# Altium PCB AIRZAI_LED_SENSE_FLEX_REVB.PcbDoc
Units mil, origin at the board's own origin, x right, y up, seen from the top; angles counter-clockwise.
Board outline 2713.44 x 4393.69 mil, 2 copper layers (Top Layer, Bottom Layer); 51 components, 36 nets, 158 pads, 68 vias.
Unrouted connection lines stored in the file: 83.
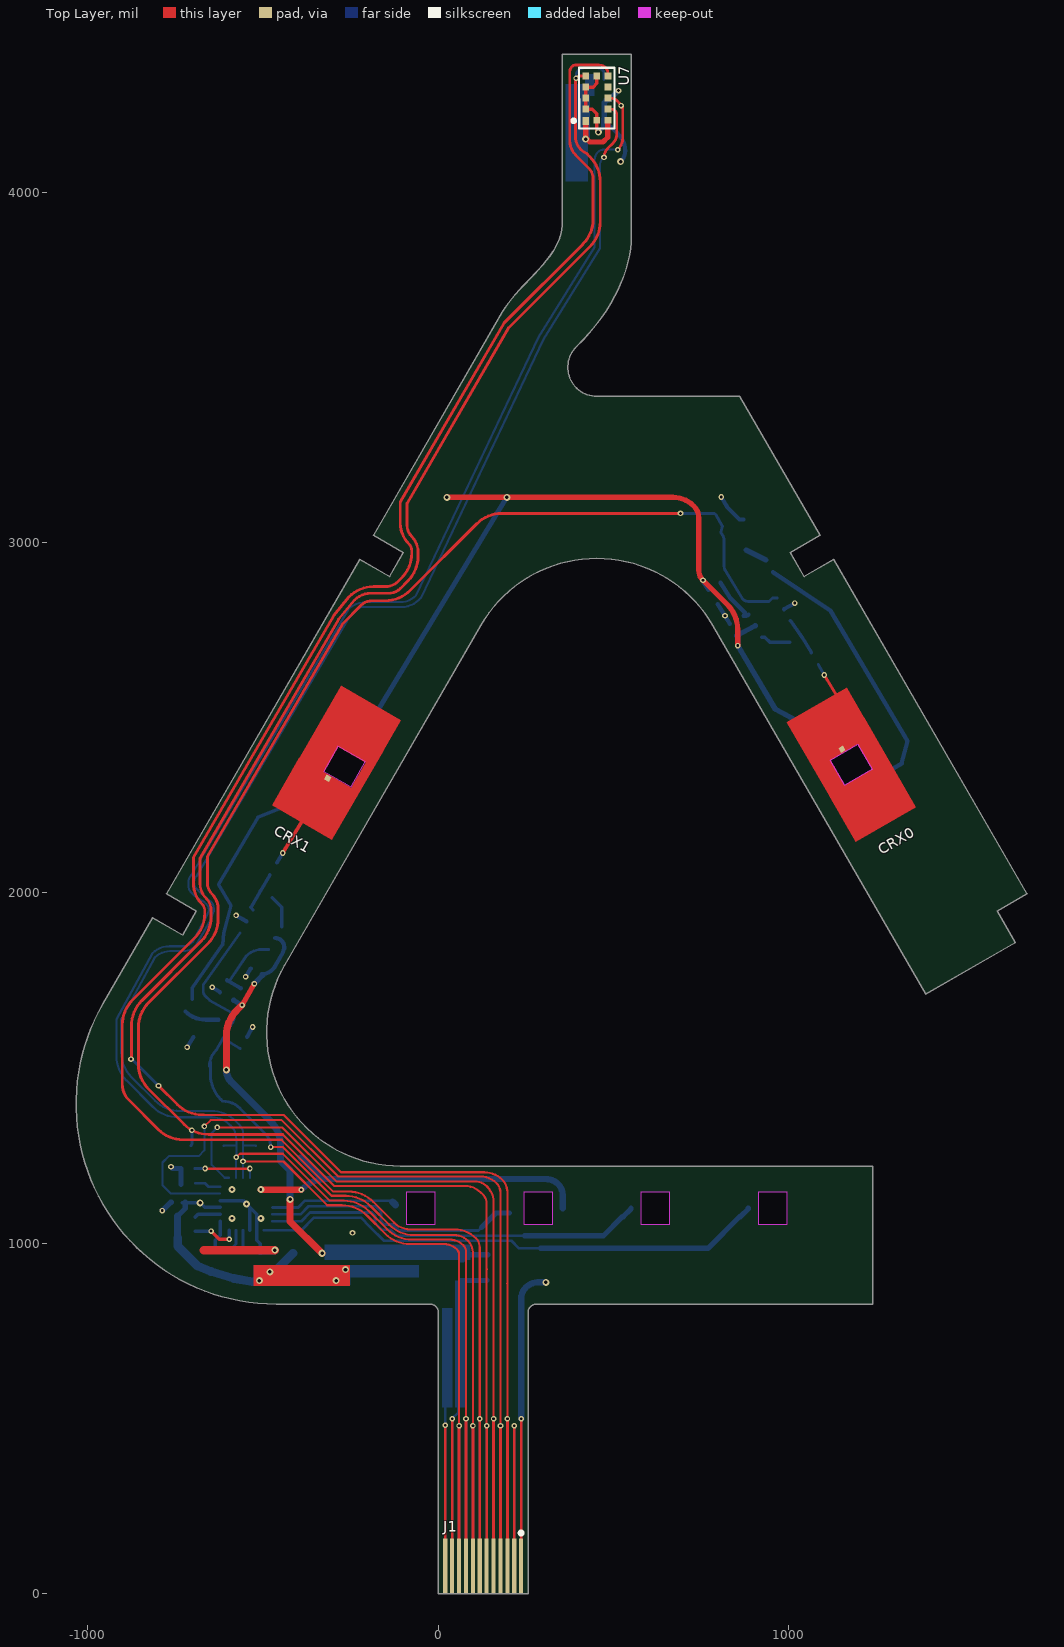
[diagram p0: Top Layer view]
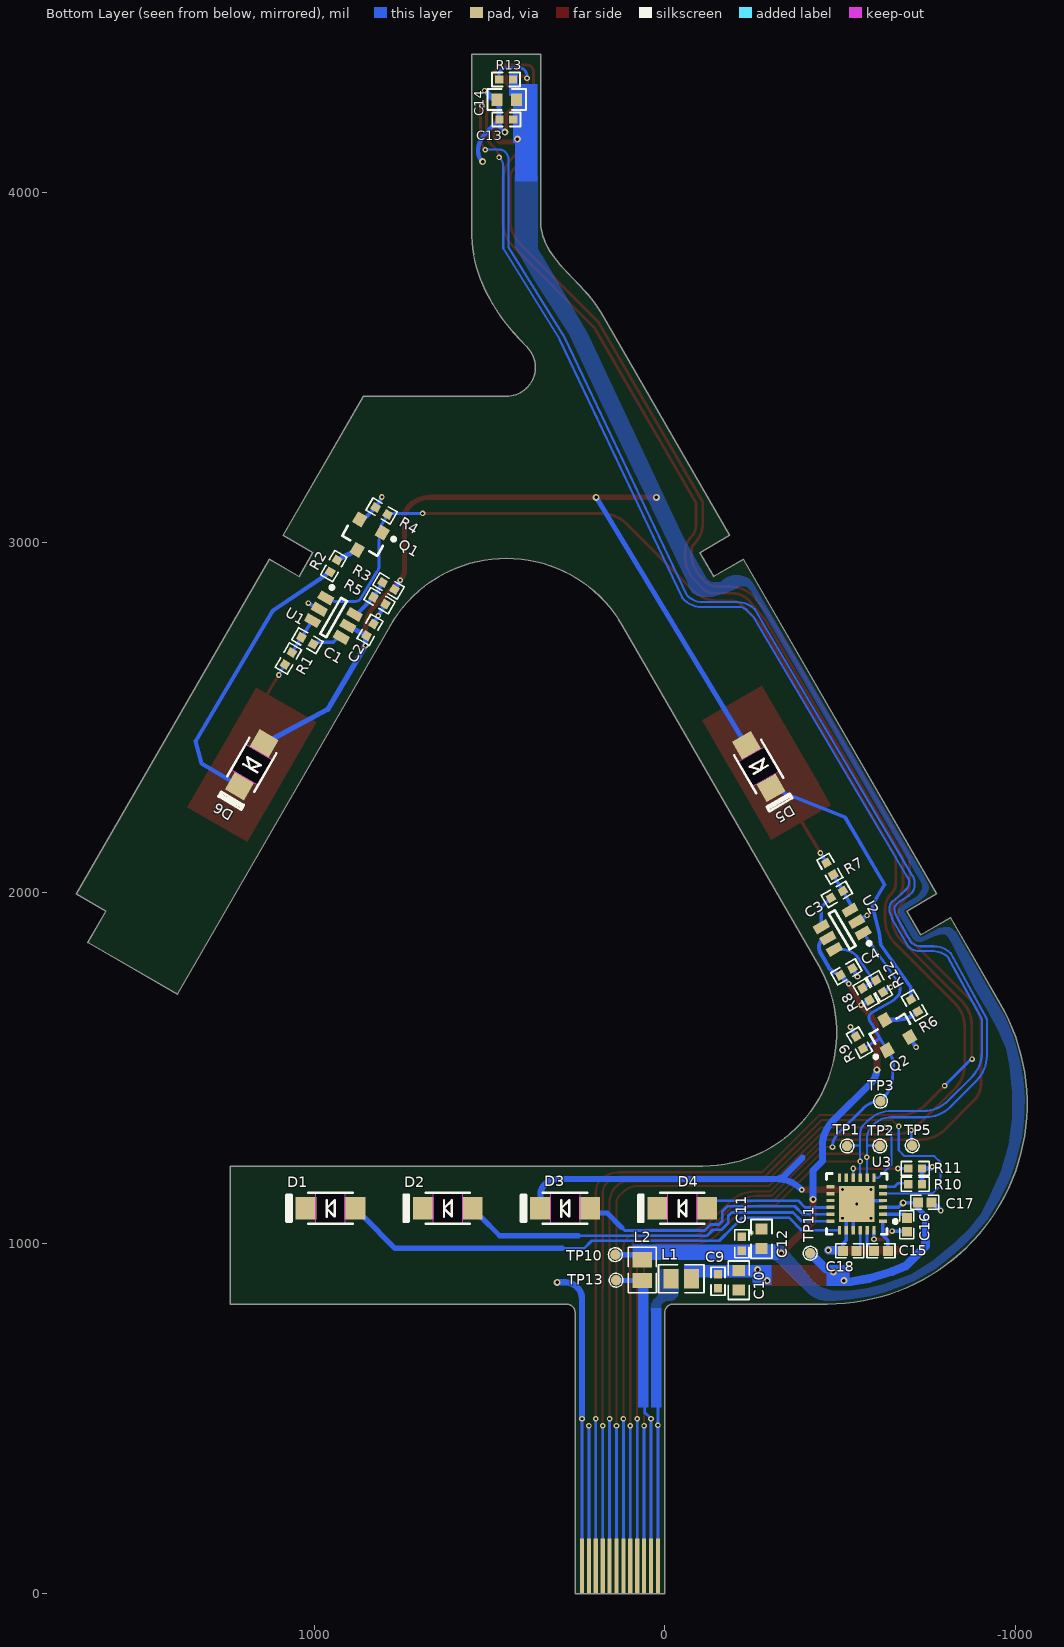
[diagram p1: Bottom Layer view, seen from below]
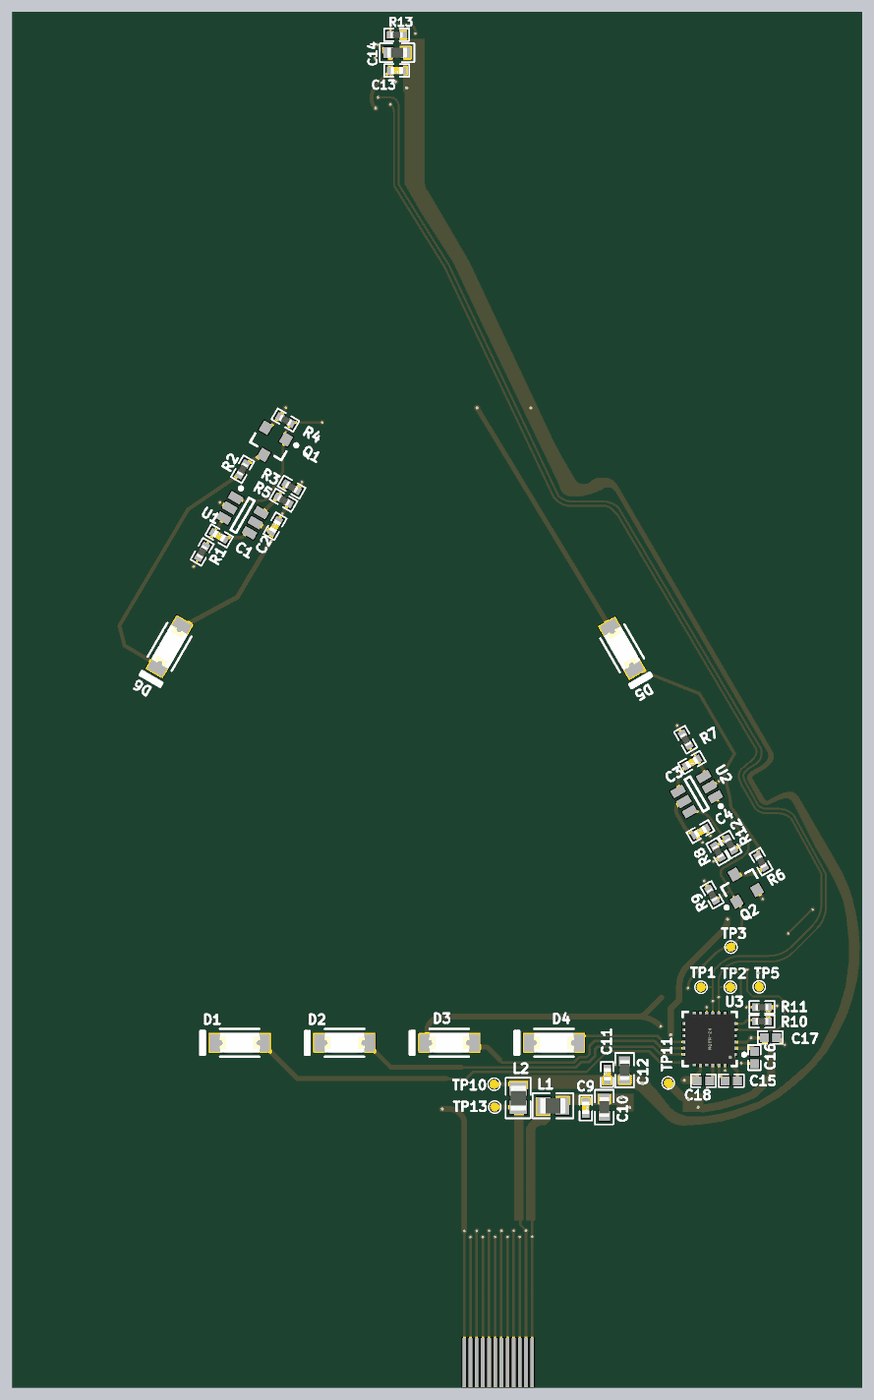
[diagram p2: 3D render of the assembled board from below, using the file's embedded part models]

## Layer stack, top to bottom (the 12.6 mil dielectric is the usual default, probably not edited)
Top Solder: solder mask 0.4, Solder Resist, Dk 3.5
Top Layer: signal copper 1.4
Dielectric 1: dielectric 12.6, FR-4, Dk 4.8
Bottom Layer: signal copper 1.4
Bottom Solder: solder mask 0.4, Solder Resist, Dk 3.5

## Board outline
-463,826.78 cw(c-462.98,1397.65) -957.36,1683.09 -815.14,1929.41 -729.91,1880.19 -690.53,1948.38 -775.77,1997.6 -224.58,2952.23 -139.35,2903.01 -99.97,2971.2 -185.21,3020.41 182.62,3657.47 cw(c465.09,3488.64) 220.1,3708.36 cw(c839.65,3165.01) 242.17,3732.54 264.96,3756.39 ccw(c-627.68,4615.35) 287.35,3780.27 ccw(c-93.59,4128.16) 308.19,3804.57 ccw(c73.79,3993.55) 326.37,3829.65 ccw(c158.18,3938.86) 340.75,3855.9 ccw(c204.05,3917.92) 350.2,3883.68 ccw(c222.06,3913.41) 353.61,3913.38 353.61,3952.75 353.61,4393.69 550.46,4393.69 550.46,3952.74 550.46,3874 cw(c239.31,3875.17) 542.24,3804.11 cw(c183.5,3887.15) 532.52,3769.79 cw(c138.88,3902.12) 519.55,3736.13 cw(c91.77,3922.61) 503.7,3703.33 cw(c24.31,3959.43) 464.84,3641.1 cw(c-49.74,4012.89) 394.16,3559.04 ccw(c452.02,3499.99) 452.02,3417.31 860.08,3417.3 1089.23,3020.38 1003.99,2971.17 1043.36,2902.98 1128.6,2952.19 1679.74,1997.53 1594.5,1948.32 1646.29,1858.61 1390.38,1711.31 782.73,2763.85 ccw(c452,2572.92) 121.28,2763.87 -439.1,1793.32 ccw(c-108.38,1602.36) -108.39,1220.47 1239.37,1220.44 1239.37,826.77 279.66,826.77 ccw(c279.78,802.89) 255.91,802.77 255.91,0 0,0 0,802.41 ccw(c-23.88,802.89) -23.39,826.77
cut-out: 912.59,1055.11 995.26,1055.11 995.26,1145.66 912.59,1145.66
cut-out: 577.94,1055.12 660.62,1055.12 660.62,1145.67 577.94,1145.67
cut-out: 243.3,1055.12 325.97,1055.12 325.97,1145.67 243.3,1145.67
cut-out: -91.36,1055.12 -8.68,1055.12 -8.68,1145.67 -91.36,1145.67
cut-out: 1159.59,2307.55 1118.49,2378.93 1196.97,2424.11 1238.06,2352.73
cut-out: -327.65,2347.93 -249.18,2302.74 -208.08,2374.12 -286.55,2419.3

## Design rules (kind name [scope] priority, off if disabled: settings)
Clearance Clearance_Board_Cutout_Electrodes [(InComponent('CRX0') OR InComponent('CRX1')) vs OnLayer('Multi-Layer')] p1: gap=0 ignorepadtopadclearanceinfootprint=FALSE
Clearance Clearance_Board_Cutout_Diodes [(InComponent('D1') OR InComponent('D2') OR InComponent('D3') OR InComponent('D4') OR InComponent('D5') OR InComponent('D6')) vs OnLayer('Multi-Layer')] p2: gap=0 ignorepadtopadclearanceinfootprint=FALSE
Clearance Clearance_Keepout [(OnLayer('Keep-Out Layer')) vs (InComponent('D1') OR InComponent('D2') OR InComponent('D3') OR InComponent('D4') OR InComponent('D5') OR InComponent('D6') OR InComponent('CRX0') OR InComponent('CRX1') OR InComponent('J1'))] p3: gap=0 ignorepadtopadclearanceinfootprint=FALSE
Clearance Clearance_GND_POLY_ELECTRODE [(InComponent('CRX0') OR InComponent('CRX1') OR InComponent('CRX2') OR InNet('NetCRX0_1') OR InNet('NetCRX1_1') OR InNet('NetCRX2_1') OR InNet('NetR4_2') OR InNet('NetR2_1') OR InNet('NetR1_1')) vs (InNet('GND') AND InPolygon)] p4: gap=30 ignorepadtopadclearanceinfootprint=FALSE
Clearance Clearance_POLYGON_KEEPOUT [(OnLayer('Keep-Out Layer')) vs (InNet('GND') AND InPolygon)] p5: gap=10 ignorepadtopadclearanceinfootprint=FALSE
Clearance Clearance_GND_POLY_REST [All vs (InNet('GND') AND InPolygon)] p6: gap=10 ignorepadtopadclearanceinfootprint=FALSE
Clearance [All] p7: gap=6 ignorepadtopadclearanceinfootprint=FALSE
MinimumSolderMaskSliver [All] p1: minsoldermaskwidth=1
PolygonConnect [All] p1: connectstyle=Direct reliefconductorwidth=10 reliefentries=4 polygonreliefangle="90 Angle" airgapwidth=10
RoomDefinition AIRZAI_LED_SENSE_FLEX_REVB [InComponentClass('AIRZAI_LED_SENSE_FLEX_REVB')] p1: confinementstyle=ConfineIn formatcopy=TRUE lockcomponents=FALSE outline -3892.14,-2713.97 10767.86,-2713.97 10767.86,6886.03 -3892.14,6886.03
RoutingVias [All] p1: holewidth=28 width=50 viastyle="Through Hole" minholewidth=8 minwidth=16 maxholewidth=28 maxwidth=50
SilkToSilkClearance [All] p1: silktosilkclearance=1
SilkToSolderMaskClearance [IsPad] p1: minsilkscreentomaskgap=2 clearancetoexposedcopper=TRUE
SolderMaskExpansion [All] p1: expansion=4
UnRoutedNet [All] p1: checkbadconnections=TRUE
Width [All] p1: maxlimit=100 minlimit=6 preferedwidth=10
26 further rules are at their usual default settings.

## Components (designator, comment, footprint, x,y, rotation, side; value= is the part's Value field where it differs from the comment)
C1 "22nF" 0402CAP 1020,2720 r210 bottom
C2 "0.1µF" 0402CAP 841,2751 r120 bottom
C3 "22nF" 0402CAP -491,1996 r330 bottom
C4 "0.1µF" 0402CAP -518.16,1775.08 r150 bottom
C9 "0.1µF" 0402CAP -152,892.17 r270 bottom
C10 "10µF" 0603 -211,895 r270 bottom
C11 "0.1µF" 0402CAP -220,999.22 r90 bottom
C12 "10µF" 0603 -276,1013 r90 bottom
C13 "0.1µF" 0402CAP 452.01,4207.25 r0 bottom
C14 "4.7µF" 0603 451,4264 r180 bottom
C15 "CAP 1uF 16V 0402(1005)" CAPC0402(1005)60_M -616.69,979 r0 bottom value=1uF
C16 "CAP 1uF 16V 0402(1005)" CAPC0402(1005)60_M -690.55,1053.06 r270 bottom value=1uF
C17 "CAP 1uF 16V 0402(1005)" CAPC0402(1005)60_M -741.73,1117.23 r0 bottom value=1uF
C18 "CAP 1uF 16V 0402(1005)" CAPC0402(1005)60_M -527.69,979 r0 bottom value=1uF
CRX0 "CONTACT POINT 1" "CONTACT_POINT_1CM _SQ - duplicate" 1178.28,2365.83 r300 top
CRX1 "CONTACT POINT 1" "CONTACT_POINT_1CM _SQ" -290.35,2372.21 r60 top
D1 "WHITE" LED1206_LTW-C230DS 953.93,1100.39 r0 bottom locked
D2 "WHITE" LED1206_LTW-C230DS 619.28,1100.4 r0 bottom locked
D3 "WHITE" LED1206_LTW-C230DS 284.63,1100.41 r0 bottom locked
D4 "WHITE" LED1206_LTW-C230DS -50.03,1100.42 r0 bottom
D5 "WHITE" LED1206_LTW-C230DS -267.86,2361.02 r240 bottom
D6 "WHITE" LED1206_LTW-C230DS 1178.28,2365.83 r300 bottom
J1 "FFC Pads" FFC_PADS 127.95,78.74 r0 top locked
L1 "CB2012T100KR" 0805 -47,899 r180 bottom value=10uH
L2 "CB2012T100KR" 0805 64,924 r90 bottom value=10uH
Q1 "NTR4003NT1G" SOT-23-3-NTR4003NT1G 858,3013 r300 bottom
Q2 "NTR4003NT1G" SOT-23-3-NTR4003NT1G -647,1604 r60 bottom
R1 "10k 0402(1005)" 0402 1074,2669 r300 bottom value=10k
R2 "100R 0402(1005)" 0402 944.64,2933 r300 bottom value=100
R3 "Jumper 0402(1005)" 0402 788.11,2876 r210 bottom value=0R
R4 "DNP 0402(1005)" 0402 808,3090 r30 bottom value=DNP
R5 "DNP 0402(1005)" 0402 814,2834 r210 bottom value=DNP
R6 "100R 0402(1005)" 0402 -712,1679.08 r60 bottom value=100
R7 "10k 0402(1005)" 0402 -471,2069 r60 bottom value=10k
R8 "Jumper 0402(1005)" 0402 -574.02,1711 r240 bottom value=0R
R9 "DNP 0402(1005)" 0402 -555.51,1573 r60 bottom value=DNP
R10 "Jumper 0402(1005)" 0402 -714.57,1168.99 r0 bottom value=0R
R11 "Jumper 0402(1005)" 0402 -714.57,1213.99 r0 bottom value=0R
R12 "DNP 0402(1005)" 0402 -613,1734 r240 bottom value=DNP
R13 "10k 0402(1005)" 0402 453,4321 r0 bottom value=10k
TP1 "Test Point" TP_0.9MM -520.09,1278 r90 bottom
TP2 "Test Point" TP_0.9MM -613.6,1278 r90 bottom
TP3 "Test Point" TP_0.9MM -615.68,1406 r90 bottom
TP5 "Test Point" TP_0.9MM -706,1279 r90 bottom
TP10 "Test Point" TP_0.9MM 141,968 r90 bottom
TP11 "Test Point" TP_0.9MM -415,972 r90 bottom
TP13 "Test Point" TP_0.9MM 139,895 r90 bottom
U1 "AT42QT1010-TSHR" SOT-23-6-AT42QT1010-TSHR 944.94,2785.89 r210 bottom
U2 "AT42QT1010-TSHR" SOT-23-6-AT42QT1010-TSHR -506.3,1895 r330 bottom
U3 "LP55231SQE/NOPB" WQFN-24-LP55231SQE/NOPB -547.74,1112.61 r0 bottom value="IC LED DRIVER RGLTR DIM 24WQFN"
U7 "VL53L0CXV0DH/1" VL53L0X 452,4268 r270 top

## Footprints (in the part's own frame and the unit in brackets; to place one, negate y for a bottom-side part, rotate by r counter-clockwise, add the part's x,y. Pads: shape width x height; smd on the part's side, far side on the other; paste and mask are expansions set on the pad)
0402 [mm] "Chip Resistor, Body 1.1x0.5mm, IPC High Density"
  rect 0.6x0.6 smd: 1(-0.5,0) 2(0.5,0)
  silkscreen extent -1.02,-0.51 1.02,0.51, body extent -0.5,-0.25 0.5,0.25, height 0.27
0402CAP [mm] "Chip Capacitor, Body 1.1x0.5mm, IPC High Density"
  rect 0.6x0.6 smd: 1(-0.5,0) 2(0.5,0)
  silkscreen extent -1.02,-0.51 1.02,0.51, body extent -0.5,-0.3 0.5,0.3, height 0.19
0603 [mm] "Chip Resistor, Body 1.6x0.8mm, IPC High Density"
  rect 0.8x0.9 smd: 1(-0.7,0) 2(0.7,0)
  silkscreen extent -1.4,-0.76 1.4,0.76, body extent -0.8,-0.41 0.8,0.4, height 0.37
0805 [mm] "Chip Resistor, Body 2.0x1.3mm, IPC High Density"
  rect 1.1x1.4 smd: 1(-0.75,0) 2(0.75,0)
  silkscreen extent -1.65,-1.02 1.65,1.02, body extent -1.02,-0.64 0.98,0.62, height 0.47
CAPC0402(1005)60_M [mm] "Chip Capacitor, Body 1.0x0.5mm, Height 0.6mm, IPC Low Density"
  rect 0.72x0.72 smd: 1(-0.5,0) 2(0.5,0)
  silkscreen extent -1.02,-0.51 1.02,0.51, body extent -0.55,-0.3 0.55,0.3, height 0.6
"CONTACT_POINT_1CM _SQ" [mm]
  rect 0.4x0.4 smd paste-2 mask-2: 1(-1.312,-0.018)
  Top Layer region: -3.216,2.5 -1.068,0.472 1.05,0.472 1.05,-2.5 5,-2.5 5,2.5
  Top Layer region: 2.48,-2.5 1.768,-1.828 -1.05,-1.828 -1.05,2.5 -5,2.5 -5,-2.5
"CONTACT_POINT_1CM _SQ - duplicate" [mm]
  rect 0.4x0.4 smd paste-2 mask-2: 1(-1.312,-0.018)
  Top Layer region: 2.48,-2.5 1.05,-1.15 -1.05,-1.15 -1.05,2.5 -5,2.5 -5,-2.5
  Top Layer region: -2.48,2.5 -1.05,1.15 1.05,1.15 1.05,-2.5 5,-2.5 5,2.5
FFC_PADS [mm] "(0.50mm"
  rect 0.3x4 smd: 1(2.75,0) 2(2.25,0) 3(1.75,0) 4(1.25,0) 5(0.75,0) 6(0.25,0) 7(-0.25,0) 8(-0.75,0) 9(-1.25,0) 10(-1.75,0) 11(-2.25,0) 12(-2.75,0)
  rect 0.3x4 smd far side: 1(2.75,0) 2(2.25,0) 3(1.75,0) 4(1.25,0) 5(0.75,0) 6(0.25,0) 7(-0.25,0) 8(-0.75,0) 9(-1.25,0) 10(-1.75,0) 11(-2.25,0) 12(-2.75,0)
  silkscreen extent 2.63,2.29 2.87,2.54
LED1206_LTW-C230DS [mm] "Chip Capacitor, Body 3.2x1.6mm, IPC High Density"
  rect 1.5x1.6 smd paste-0.1 mask+0.07: 1(1.775,0) 2(-1.775,0)
  silkscreen extent -1.6,-1.13 3.19,1.13, body extent -1.63,-0.8 1.63,0.8, height 0.31
SOT-23-3-NTR4003NT1G [mm] "SOT23, 3-Leads, Body 2.92x1.3mm, Pitch 0.95mm"
  rect 0.9x0.8 smd: 1(-1,0.95) 2(-1,-0.95) 3(1,0)
  silkscreen extent -1.12,-1.46 0.65,2.02, body extent -0.65,-1.46 0.65,1.46, height 1.11
SOT-23-6-AT42QT1010-TSHR [mm] "SOT23, 6-Leads, Body 2.9x1.6mm, Pitch 0.95mm, Lead Span 2.8mm, IPC Medium Density"
  rect 1.1x0.65 smd: 1(-1.2,0.95) 2(-1.2,0) 3(-1.2,-0.95) 4(1.2,-0.95) 5(1.2,0) 6(1.2,0.95)
  silkscreen extent -1.32,-1.5 0.25,1.95, body extent -0.88,-1.5 0.88,1.5, height 1.45
TP_0.9MM [mm] "0.9MM DIA TESTPOINT"
  round 0.75 smd paste-5 mask+0.05: 1(0,0)
  silkscreen extent -0.5,-0.5 0.5,0.5
VL53L0X [mm]
  rect 0.58x0.5 smd: 1(1.64,-0.8)
  rect 0.5x0.5 smd: 2(0.8,-0.8) 3(0,-0.8) 4(-0.8,-0.8) 5(-1.6,-0.8) 6(-1.6,0) 7(-1.6,0.8) 8(-0.8,0.8) 9(0,0.8) 10(0.8,0.8) 11(1.6,0.8) 12(1.6,0)
  silkscreen extent -2.2,-1.79 2.2,1.3, body extent -2.2,-1.3 2.2,1.3, height 3.72
WQFN-24-LP55231SQE/NOPB [mm] "QFN, 24-Leads, Body 3.97x3.97mm, Pitch 0.50mm, Thermal Pad 2.60x2.60mm, IPC Medium Density"
  rect 0.6x0.25 smd: 1(-1.9,1.25) 2(-1.9,0.75) 3(-1.9,0.25) 4(-1.9,-0.25) 5(-1.9,-0.75) 6(-1.9,-1.25) 13(1.9,-1.25) 14(1.9,-0.75) 15(1.9,-0.25) 16(1.9,0.25) 17(1.9,0.75) 18(1.9,1.25)
  rect 0.25x0.6 smd: 7(-1.25,-1.9) 8(-0.75,-1.9) 9(-0.25,-1.9) 10(0.25,-1.9) 11(0.75,-1.9) 12(1.25,-1.9) 19(1.25,1.9) 20(0.75,1.9) 21(0.25,1.9) 22(-0.25,1.9) 23(-0.75,1.9) 24(-1.25,1.9)
  rect 2.6x2.6 smd: 25(0,0)
  silkscreen extent -2.92,-2.2 2.2,2.2, body extent -2.01,-2.01 2.01,2.01, height 0.8

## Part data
C1 C3: library part C0402-100n, "Capacitor, X7R, ±10%", Case/Package=0402, Case Code (Metric)=1005, Dielectric=X7R, Manufacturer=TDK, Manufacturer Part Number=CGA2B2X7R1E223K050BA, Max Operating Temperature=125°C, Min Operating Temperature=-55°C, Package Quantity=1, Ratings=AEC-Q200, Supplier Part Number 1=445-5609-1-ND, Tolerance=10%, Voltage Rating=25V
C2 C4 C9 C11 C13: library part C0402-100n, "Capacitor, X7R, ±10%", Case-EIA=0402, Case-Metric=1005, Manufacturer=TDK, Manufacturer Part Number=C1005X7R1C104K, Rated Voltage="16 V", Supplier Part Number 1=445-4952-2-ND, Tolerance=±20%
C10 C12: library part C0402-100n, "Capacitor, X7R, ±10%", Case-EIA=0603, Case-Metric=1608, Manufacturer=MURATA, Manufacturer Part Number=GRM188R60J106ME47D, Rated Voltage="6.3 V", Supplier Part Number 1=490-3896-6-ND, Tolerance=±20%
C14: library part "C0603-1µ0 X7R", "Capacitor, X7R, ±10%", Case-EIA=0402, Case-Metric=1005, Manufacturer=TDK, Manufacturer Part Number=C1005X5R0J475M, Rated Voltage="6.3 V", Supplier Part Number 1=445-7395-2-ND, Tolerance=±20%
C15 C16 C17 C18: library part CAP, "CAP 1uF 16V ±10% 0402 (1005 Metric) Thickness 0.6mm SMD", Case-EIA=0402, Case-Metric=1005, Manufacturer="Taiyo Yuden", Manufacturer Part Number=JMK105C6105KV-F, Rated Voltage="6.3 V", Supplier Part Number 1=587-3381-1-ND, Tolerance=±10%
CRX0 CRX1: library part WIRE_POINT
D1 D2 D3 D4 D5 D6: library part LED_LTW-C230DS, Case-EIA=1206, Case-Metric=3216, Manufacturer=LITEON, Manufacturer Part Number=LTW-C230DS, Supplier Part Number 1=160-2221-1-ND
J1: library part FFC_PADS, "0.5 mm Pitch FFC Pads"
L1 L2: "Inductor, 10 µH, 0.5A, 0.65 ohm, SMD", Case/Package=0805, Case Code (Metric)=2012, Current Rating=520mA, DC Resistance (DCR)=500mR, Inductance=10uH, Inductance Tolerance=10%, Manufacturer="Taiyo Yuden", Max DC Current=200mA, Max Operating Temperature=105°C, Min Operating Temperature=-40°C, Package Quantity=3000, Self Resonant Frequency=32MHz, Supplier Part Number 1=587-2452-1-ND, Test Frequency=2.52MHz, Value1="0.65 ohm", Value2=0.5A, ValueDisplayed=10µH
Q1 Q2: "N-Channel 30V 500mA (Ta) 690mW (Ta) Surface Mount SOT-23-3 (TO-236)", Case/Package=SOT-23-3, Continuous Drain Current (ID)=500mA, Drain to Source Breakdown Voltage=30V, Drain to Source Resistance=1R, Gate to Source Voltage (Vgs)=20V, Input Capacitance=21pF, Manufacturer="ON Semiconductor", Max Operating Temperature=150°C, Max Power Dissipation=690mW, Min Operating Temperature=-55°C, Package Quantity=1, Supplier Part Number 1=NTR4003NT1GOSCT-ND, Threshold Voltage=1.4V
R1 R7 R13: library part RES, "10k 0.063W 1% 0402 (1005 Metric)  SMD", Case-EIA=0402, Case-Metric=1005, Manufacturer=Yageo, Manufacturer Part Number=RC0402FR-0710KL, Power=0.063W, Supplier Part Number 1=311-10.0KLRCT-ND, Tolerance=None
R2 R6: library part RES, "100 0.063W 1% 0402 (1005 Metric)  SMD", Case-EIA=0402, Case-Metric=1005, Manufacturer=Yageo, Manufacturer Part Number=RC0402FR-07100RL, Power=None, Supplier Part Number 1=311-100LRCT-ND
R3 R8 R10 R11: library part RES, "Jumper 0402 (1005 Metric)", Case-EIA=0402, Case-Metric=1005, Manufacturer=Panasonic, Manufacturer Part Number=ERJ-2GE0R00X, Power=None, Supplier Part Number 1=P0.0JCT-ND
R4 R5 R9 R12: library part RES, "DNP", Case-EIA=0402, Case-Metric=1005, Power="0.0625 W", Tolerance=None
U1 U2: "One-channel Touch Sensor IC with Reset Timer, -40° to +85° C, 6-pin SOT23", Supplier Part Number 1=AT42QT1010-TSHRCT-ND
U3: "Imported", Case-EIA=24-WQFN, Manufacturer=TI, Supplier Part Number 1=296-39059-1-ND, Tolerance=None
U7: library part VL53L0X, Case-EIA=LGA12, Manufacturer=ST, Supplier Part Number 1=497-16538-1-ND, Tolerance=None

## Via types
v1: diameter 16, hole 8, Top Layer to Bottom Layer, tented both sides, 48 vias
v2: diameter 20, hole 10, Top Layer to Bottom Layer, tented both sides, 15 vias
v3: diameter 20, hole 8, Top Layer to Bottom Layer, 5 vias

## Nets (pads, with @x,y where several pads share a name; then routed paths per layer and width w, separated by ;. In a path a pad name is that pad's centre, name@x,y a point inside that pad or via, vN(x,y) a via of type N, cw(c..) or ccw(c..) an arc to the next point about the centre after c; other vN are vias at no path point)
3V3: C2.1 C4.1 C11.1 C12.1 C13.1 C14.2 D5.2 D6.2 L2.2 R3.2 R8.2 R13.1 TP10.1 U1.5 U2.5 U7.1 U7.11 | length 3880.9
  Top Layer w15: v1(-560,1680) v1(-525.05,1741) ; v2(24,3129) 668.64,3129 cw(c668.64,3043.64) 729,3104 cw(c695.2,3070.2) 743,3070.2 743,2921.23 ccw(c783.97,2921.23) v1(755,2892.26) 824.71,2822.55 cw(c754,2751.84) 854,2751.84 v1(854,2706) ; U7.1 v2(420.5,4151.32) 423.68,4151.32 432,4143 470,4143 483.5,4156.5 U7.11@483.5,4201.86
  Top Layer w20: v2(-605,1495) -605,1593.58 cw(c-505,1593.58) -575.71,1664.29 v1(-560,1680) ; v2(-423,1126) -423,1063 v2(-332,972)
  Bottom Layer w12: C4.1@-504.11,1768.24 ccw(c-504.11,1810.11) -474.5,1780.5 -469,1786 -443,1831.47 -440,1842 -440,1845.99 ccw(c-465.39,1845.99) U2.5
  Bottom Layer w15: R8.2 v1(-560,1680) ; v1(-525.05,1741) -525.05,1741.65 -501.34,1765.36 C4.1@-501,1766 ; D5.2 v2(195.72,3129.17) ; L2.2 69.91,953.53 84.38,968 TP10.1 ; v1(755,2892.26) R3.2 ; U1.5 C2.1 854,2730.79 v1(854,2706) 962,2524 D6.2
  Bottom Layer w20: v2(-605,1495) ccw(c-556.72,1495) -590.86,1460.86 -479.29,1349.29 cw(c-550,1278.58) -450,1278.58 -450,1235.77 -422.69,1208.46 -422.69,1126.31 v2(-423,1126)
+5V: C9.1 C10.1 C17.2 L1.2 TP11.1 U3.3 | length 634.2
  Bottom Layer w10: C17.2@-730.32,1115.77 -722.05,1115.77 -679.74,1115.77 -666.74,1102.77 U3.3
  Bottom Layer w15: -744.8,994.83 -743.8,993.83 ; -743.8,1078.55 -722.05,1100.3 -722.05,1115.77 C17.2
  Bottom Layer w20: -743.8,1016.44 -743.8,1078.55
  Bottom Layer w25: -743.8,1016.44 -743.8,993.83 -743.8,992.27 -686.76,935.24 -649,920 -583.14,900 -530,891 -477,892 ; v2(-481,919) -481,920 -474.5,926.5 -460.5,926.5 TP11.1
  other v2: -511,894 -292,894 -265,925 -680.02,1116.05
CAP1_TOUCH_OUT: J1.6 Q1.1 R4.1 TP5.1 U1.1 | length 5668.8
  Top Layer w6: -444,1311 -297,1164 76,1164 cw(c76,1101.23) 120.38,1145.62 129,1137 cw(c107.77,1115.77) 137.8,1115.77 137.8,926.29 ; v1(137.8,480) 137.8,926.29 ; 138,926.5 137.8,926.29
  Top Layer w8: -444,1311 -655.58,1311 cw(c-655.58,1411) -726.29,1340.29 -826.71,1440.71 cw(c-756,1511.42) -856,1511.42 -856,1616.15 cw(c-756,1616.15) -826.71,1686.86 -657.74,1855.84 ccw(c-728.45,1926.55) -628.45,1926.55 -628.45,1954.63 ccw(c-688.37,1954.63) -646,1997 cw(c-614.62,2028.38) -659,2028.38 -659,2103 -273.55,2767.9 -220.49,2820.96 cw(c-189,2789.47) -189,2834 -151.47,2834 ccw(c-151.47,2934) -80.76,2863.29 109.66,3053.71 cw(c180.37,2983) 180.37,3083 v1(691,3083) ; J1.6@137.8,78.74 v1(137.8,480)
  Bottom Layer w8: TP5.1 ccw(c-712.47,1285.47) -703.32,1285.47 v1(-703.32,1323) ; J1.6@137.8,78.74 v1(137.8,480) ; v1(691,3083) 788.11,3083 R4.1 810.66,3047.11 Q1.1 cw(c783.19,3005.66) 815.34,3005.66 815.34,2932.03 ccw(c838.08,2932.03) 822,2915.95 869,2838.08 ccw(c883.39,2852.47) 883.39,2832.12 943.67,2832.12 953.46,2841.91 U1.1
CAP2_TOUCH_OUT: J1.8 Q2.1 R9.1 TP3.1 U2.1 | length 2854.2
  Top Layer w6: v1(-478.49,1275) -443.97,1275 -304.97,1136 -264.42,1136 cw(c-264.42,1036) -193.71,1106.71 -140.29,1053.29 ccw(c-69.58,1124) -69.58,1024 43.96,1024 cw(c43.96,965.96) 85,1007 cw(c52.59,974.59) 98.43,974.59 98.43,929.43 ; v1(98.43,480) 98.43,929.43 ; 99,930 98.43,929.43
  Top Layer w8: J1.8@98.43,78.74 v1(98.43,480)
  Bottom Layer w8: -653.32,1505.27 cw(c-588.36,1505.27) Q2.1 -613.96,1586 ; -650.32,1517.27 -650.32,1482.06 ccw(c-550.32,1482.06) -621.03,1411.35 TP3.1 cw(c-615.68,1336) -566.18,1385.5 -494.6,1313.92 cw(c-533.56,1275) v1(-478.49,1275) ; U2.1 -671.14,1738 -671,1737.86 -671,1721.15 ccw(c-648.74,1721.15) -664.48,1705.41 -653.32,1694.25 -590,1658 -586.91,1654.91 cw(c-596.81,1645) -582.8,1645 -582.8,1644.37 cw(c-607.37,1644.37) -590,1627 -613.96,1586 ; R9.1 -613.96,1586 ; J1.8@98.43,78.74 v1(98.43,480)
EN: J1.4 U3.5 | length 2851.7
  Top Layer w6: v1(-667.55,1334) -649.55,1352 -447.08,1352 -286.08,1191 120.13,1191 cw(c120.13,1126.13) 166,1172 cw(c139.44,1145.44) 177,1145.44 177,870.52 177.17,870.35 v1(177.17,480)
  Top Layer w8: J1.4@177.17,78.74 v1(177.17,480)
  Bottom Layer w6: v1(-667.55,1334) -667.55,1265.61 -684.16,1249 -769,1249 -787,1231 -787,1166.16 -762.98,1142.14 U3.5
  Bottom Layer w8: J1.4@177.17,78.74 v1(177.17,480)
GND: C2.2 C4.2 C9.2 C10.2 C11.2 C12.2 C13.2 C14.1 C17.1 C18.2 D1.1 D2.1 D3.1 D4.1 J1.1 J1.2 Q1.2 Q2.2 R4.2 R5.2 R9.2 R10.1 R11.1 R12.2 U1.2 U2.2 U3.4 U3.20 U3.21 U3.25 U7.2 U7.3 U7.4 U7.6 U7.12 | length 4613.5
  Top Layer w8: J1.2@216.54,78.74 v1(216.54,480) ; J1.1@236.22,78.74 v1(236.22,499.74)
  Top Layer w10: U7.6 452,4310 441.5,4299.5 U7.4 U7.3 U7.2 439.49,4236.5 452,4223.99 U7.12 452,4175.5 v2(456.5,4171)
  Top Layer w18: v3(-506.8,1153.56) v1(-391,1153)
  Top Layer w25: -668.69,980.83 v2(-466.69,980.83)
  Bottom Layer w8: J1.2@216.54,78.74 v1(216.54,480) ; J1.1@236.22,78.74 v1(236.22,499.74)
  Bottom Layer w10: U3.4 -557.58,1122.46 v3(-547.74,1112.61) U3.25@-537.9,1102.77 ; U3.21 U3.25@-537.9,1102.77 ; C18.2 -508,999.14 -518.21,1009.35 U3.20 -518.21,1083.09 U3.25@-537.9,1102.77
  Bottom Layer w12: v1(-717,1560) Q2.2 ; v1(-645,1731) R12.2 ; v1(-577.27,1936) U2.2 ; v1(-550,1761) C4.2 ; R9.2 v1(-530.09,1617.64) ; v2(456.5,4171) 469.96,4184.46 469.96,4205.51 C13.2 512.54,4166.4 cw(c463.14,4117) 533,4117 cw(c491.96,4117) 520.98,4087.98 v2(520,4087) ; R5.2 v1(817.84,2791) C2.2 ; v1(807.11,3130) R4.2 849.19,3075.7 849.29,3075.7 859.19,3065.8 Q1.2 ; U1.2 v1(1017,2827.11)
  Bottom Layer w15: v1(-787.69,1093.83) -764.28,1117.23 C17.1 ; v1(-762.98,1218.83) -758.14,1213.99 R11.1 R10.1 ; C13.2 ccw(c468.53,4210.41) 473,4210.41 473,4255 476.13,4258.13 ccw(c470.25,4264) C14.1 ; C14.1@487,4263 513.5,4289.5 v1(514,4289.5)
  Bottom Layer w18: -393,1245 -341.49,1193.49 ccw(c-318.58,1216.4) -318.58,1184 ; v1(-391,1153) -389.29,1154.71 cw(c-318.58,1084) -318.58,1184 ; v1(236.22,499.74) 236.22,841.73 cw(c283.27,841.73) 250,875 cw(c283.8,841.2) 283.8,889 v2(307,889) ; D3.1 354.51,1138.79 ccw(c311.79,1138.79) 342,1169 ccw(c305.79,1132.79) 305.79,1184 -318.58,1184
  Bottom Layer w25: C18.2 -506.17,980.83 v2(-466.69,980.83)
  other v1: -245,1030
  other v3: -588.69,1071.67 -506.8,1071.67 -588.69,1153.56
INT: J1.5 U3.7 | length 2525.9
  Top Layer w6: v1(-631,1331) -445.17,1331 -291.17,1177 103.91,1177 cw(c103.91,1127.37) 139,1162.46 cw(c94.38,1117.85) 157.48,1117.85 v1(157.48,499.74)
  Top Layer w8: J1.5@157.48,78.74 v1(157.48,499.74)
  Bottom Layer w6: v1(-631,1331) -647,1315 -647,1224.47 -609.95,1187.42 U3.7
  Bottom Layer w8: J1.5@157.48,78.74 v1(157.48,499.74)
NetC1_1: C1.1 R1.1 U1.3 | length 108.9
  Bottom Layer w10: U1.3 C1.1 R1.1
NetC1_2: C1.2 U1.4 | length 85.4
  Bottom Layer w10: U1.4 931.4,2729.88 946.23,2715.05 C1.2@1002,2715.05
NetC3_1: C3.1 R7.1 U2.3 | length 117.9
  Bottom Layer w8: U2.3@-535,1958.68 U2.3
  Bottom Layer w10: U2.3@-535,1958.68 C3.1 R7.1
NetC3_2: C3.2 U2.4 | length 93.7
  Bottom Layer w10: C3.2 -446.68,1958.89 U2.4
NetC15_1: C15.1 U3.1 | length 90.1
  Bottom Layer w10: C15.1 -636.37,1009.14 -622.54,1022.97 U3.1
NetC15_2: C15.2 U3.23 | length 67
  Bottom Layer w8: C15.2 -577.27,998.73 U3.23
NetC16_1: C16.1 U3.2 | length 75.2
  Bottom Layer w10: C16.1@-694.28,1074.67 -685.87,1083.09 U3.2
NetC16_2: C16.2 U3.24 | length 135.8
  Top Layer w10: v1(-648.57,1035.3) -625.26,1011.99 v1(-596.95,1011.99) v1@-596.95,1008.99
  Bottom Layer w10: C16.2@-694.28,1035.3 v1(-648.57,1035.3) ; v1(-596.95,1011.99) U3.24
NetC18_1: C18.1 U3.22 | length 61.8
  Bottom Layer w8: U3.22 -557.58,986.21 C18.1@-550.37,979
NetCRX0_1: CRX0.1 R1.2 | length 269.4
  Top Layer w8: v1(1101,2622) 1174.17,2501.29 CRX0.1
  Bottom Layer w8: R1.2 v1(1101,2622)
NetCRX1_1: CRX1.1 R7.2 | length 281.6
  Top Layer w10: v1(-444,2114) CRX1.1@-315.53,2327.08
  Bottom Layer w10: R7.2 v1(-444,2114)
NetD1_2: D1.2 U3.19 | length 1482.2
  Bottom Layer w8: U3.19 -390.19,1037.81 -354.49,1073.51 -221.13,1073.51 -195,1047.38 -195,1047.2 -155.42,1007.62 208.38,1007.62 230,986 292,986
  Bottom Layer w15: 292,986 769.65,986 860.04,1076.4 862.01,1076.4 884.04,1098.43 D1.2
NetD2_2: D2.2 U3.18 | length 1105.8
  Bottom Layer w8: U3.18 -390.79,1063.4 -366.19,1088 -190,1088 -181,1079 -181,1058 -162,1039 -137,1039 -120,1022 246,1022
  Bottom Layer w15: 246,1022 470.99,1022 525.4,1076.41 527.37,1076.41 549.39,1098.43 D2.2
NetD3_2: D3.2 U3.17 | length 750.5
  Bottom Layer w8: U3.17 -393.91,1083.09 -371,1106 -179,1106 -164,1091 -164,1064 -154,1054 -130.22,1054 -113.22,1037 114.43,1037 123,1045.57
  Bottom Layer w15: 123,1045.57 164.17,1086.74 D3.2@203.05,1086.74
NetD4_2: D4.2 U3.16 | length 364.4
  Bottom Layer w8: U3.16 -400,1102.77 -380.77,1122 D4.2@-134.22,1122
  Bottom Layer w10: D4.2@-134.22,1122 D4.2@-130.22,1118
  Bottom Layer w20: D4.2@-130.22,1118 D4.2@-121.67,1109.46
NetD5_1: D5.1 R6.2 | length 818.2
  Bottom Layer w10: R6.2 -702.16,1729.84 -702,1730 -615.68,1853 -612,1886 -591.82,1963.83 -627,2023.63 -515,2216 D5.1
NetD6_1: D6.1 R2.2 | length 822.3
  Bottom Layer w12: R2.2 1118.92,2805 1338.48,2433.56 1322.05,2369.65 D6.1
NetJ1_11: J1.11 L2.1 TP13.1 | length 997.2
  Top Layer w8: J1.11@39.37,78.74 v1(39.37,500)
  Bottom Layer w8: J1.11@39.37,78.74 v1(39.37,500) 39.37,500.37 57,518 57,571 56,570
  Bottom Layer w15: L2.1 TP13.1
NetJ1_12: J1.12 L1.1 | length 885.5
  Top Layer w8: J1.12@19.68,78.74 v1(19.68,481)
  Bottom Layer w8: J1.12@19.68,78.74 v1(19.68,481) 19.68,562
NetQ1_3: Q1.3 R2.1 | length 64
  Bottom Layer w15: Q1.3 R2.1
NetQ2_3: Q2.3 R6.1 | length 100.9
  Bottom Layer w12: R6.1 ccw(c-664.06,1719.82) -664.06,1638.1 Q2.3
NetR3_1: R3.1 R5.1 U1.6 | length 137.2
  Bottom Layer w12: R3.1 R5.1 874.32,2800.57 874.32,2794.61 870.71,2791 876.48,2791 ccw(c876.48,2803.51) U1.6
NetR8_1: R8.1 R12.1 U2.6 | length 205
  Bottom Layer w8: R12.1@-603.06,1750.99 -594.1,1752.69 -548,1820.34 cw(c-502.98,1775.31) -502.98,1838.99 U2.6
  Bottom Layer w12: R12.1@-603.06,1750.99 R8.1
NetR10_2: R10.2 U3.6 | length 75.6
  Bottom Layer w8: R10.2@-694,1171.83 -665.41,1171.83 -655.41,1161.83 U3.6
NetR11_2: R11.2 U3.10 | length 186.4
  Top Layer w6: v1(-665.57,1213.74) -664.83,1212.99 v1@-538.9,1212.99
  Top Layer w8: v1@-538.9,1212.99 v1(-537.9,1213.99)
  Bottom Layer w6: U3.10 v1(-537.9,1213.99)
  Bottom Layer w8: R11.2 -665.83,1213.99 v1(-665.57,1213.74) ; v1(-537.9,1213.99) v1@-537.9,1215.99
SCL: J1.10 TP1.1 U3.9 U7.10 | length 5932.2
  Top Layer w6: v1(-557.58,1234) -442,1234 -317,1109 -274.42,1109 cw(c-274.42,1009) -203.71,1079.71 -151.29,1027.29 ccw(c-80.58,1098) -80.58,998 16.79,998 cw(c16.79,946.79) 53,983 cw(c38.38,968.38) 59.06,968.38 v1(59.06,480)
  Top Layer w8: J1.10@59.06,78.74 v1(59.06,480) ; v1(472.68,4099) cw(c508.14,4099) 483.07,4124.07 498.39,4139.39 ccw(c472.79,4165) 509,4165 509,4218.51 ccw(c488.51,4218.51) 503,4233 ccw(c494.54,4224.54) 494.54,4236.5 U7.10
  Bottom Layer w6: U3.9 v1(-557.58,1234) -557.58,1279 ; TP1.1 ccw(c-522.51,1275.59) -522.51,1279 -557.58,1279 ; v1(472.68,4099) 472.68,4101.68 ccw(c500.9,4073.47) 461,4073.47 461,3839.84 299.86,3580.26 -50,2842 -56,2836 cw(c-104.28,2884.28) -104.28,2816 -212,2816 ccw(c-212,2784.72) -234.11,2806.84 -253.65,2787.31 -690.55,2048 ccw(c-674.98,2032.43) -697,2032.43 -697,2029 ccw(c-672.08,2029) -689.7,2011.38 -676.16,1997.84 -648.57,1975 cw(c-666.86,1956.71) -641,1956.71 -641,1946.92 -649.15,1925.26 -693.49,1848.49 cw(c-728.48,1883.48) -728.48,1834 -766.1,1834 ccw(c-766.1,1773.8) -808.67,1816.37 -905,1640 -905,1545.42 ccw(c-805,1545.42) -875.71,1474.71 -808.29,1407.29 ccw(c-737.58,1478) -737.58,1378 -648.42,1378 cw(c-648.42,1278) -577.71,1348.71 -568,1339 cw(c-593.15,1313.85) -557.58,1313.85 -557.58,1279
  Bottom Layer w8: J1.10@59.06,78.74 v1(59.06,480)
SDA: J1.9 TP2.1 U3.8 U7.9 | length 6081.4
  Top Layer w6: v1(-576.57,1245.99) -566.56,1256 -444,1256 -310,1122 -269.42,1122 cw(c-269.42,1022) -198.71,1092.71 -146.29,1040.29 ccw(c-75.58,1111) -75.58,1011 32,1011 cw(c32,955.47) 71.26,994.74 72,994 cw(c55.73,977.73) 78.74,977.73 v1(78.74,499.74)
  Top Layer w8: J1.9@78.74,78.74 v1(78.74,499.74) ; U7.9 490.97,4268 cw(c490.97,4238.97) 511.5,4259.5 cw(c465.63,4213.63) v1(521.48,4246.62) cw(c510.56,4235.7) 526,4235.7 526,4154.8 cw(c478.2,4154.8) v1(512,4121)
  Bottom Layer w6: TP2.1 cw(c-611.18,1275.59) -611.18,1279 -576.57,1279 ; U3.8 -577.27,1241.3 v1@-576.57,1241.99 ; v1(-576.57,1245.99) -576.57,1279 ; v1(512,4121) 471.9,4121 ccw(c471.9,4097.1) 455,4114 ccw(c476.73,4092.27) 446,4092.27 446,3843 286,3586 -64,2848.49 cw(c-108.63,2893.12) -108.63,2830 -207.74,2830 ccw(c-207.74,2760.9) -256.6,2809.76 -705,2051 ccw(c-685.69,2031.69) -713,2031.69 -713,2022 ccw(c-681.37,2022) -703.73,1999.63 -696.17,1992.07 -668,1974 -661.36,1967.36 cw(c-676.73,1952) -655,1952 -658.4,1940.2 -663,1931 -702,1859.59 cw(c-729.97,1887.56) -729.97,1848 -767.72,1848 ccw(c-767.72,1779.72) -816,1828 -919,1639.42 -919,1535.48 ccw(c-819,1535.48) -889.71,1464.77 -814.23,1389.29 ccw(c-743.52,1460) -743.52,1360 -646,1360 cw(c-646,1289.6) -596.22,1339.38 -591.84,1335 cw(c-628.69,1298.15) -576.57,1298.15 -576.57,1279
  Bottom Layer w8: J1.9@78.74,78.74 v1(78.74,499.74) v1@79,500
TOFINT: J1.7 U7.7 | length 6132.2
  Top Layer w6: -448,1296 -300,1148 -256.42,1148 cw(c-256.42,1048) -185.71,1118.71 -126,1059 ccw(c-80.13,1104.87) -80.13,1040 45.23,1040 cw(c45.23,951.23) 108,1014 cw(c83.59,989.59) 118.11,989.59 118.11,933.89 ; 118,934 118.11,933.89 ; v1(118.11,499.74) 118.11,933.89
  Top Layer w8: -448,1296 -728.58,1296 cw(c-728.58,1396) -799.29,1325.29 -882.91,1408.91 cw(c-836.82,1455) -902,1455 -902,1623.54 cw(c-802,1623.54) -872.71,1694.25 -695.73,1871.23 ccw(c-766.44,1941.94) -666.44,1941.94 -666.44,1949.2 ccw(c-693.76,1949.2) -674.44,1968.52 cw(c-615.2,2027.76) -698.98,2027.76 -698.98,2101 -298.8,2791.31 -255.63,2844.88 cw(c-184.92,2774.17) -184.92,2874.17 -150.8,2874.17 ccw(c-150.8,2924.8) -115,2889 -105.29,2898.71 ccw(c-176,2969.42) -76,2969.42 -76,2976.69 ccw(c-103.31,2976.69) -84,2996 cw(c-24.75,3055.25) -108.54,3055.25 -108.54,3115.47 188,3627 412.21,3851.21 ccw(c341.5,3921.92) 441.5,3921.92 441.5,4038 ccw(c397.86,4038) 428.72,4068.86 403.11,4094.46 391.79,4105.79 cw(c432.31,4146.31) 375,4146.31 375,4343.51 cw(c395.49,4343.51) 381,4358 cw(c391.85,4347.15) 391.85,4362.5 458.47,4362.5 cw(c458.47,4335.59) 477.5,4354.61 cw(c463.01,4340.13) 483.5,4340.13 U7.7 ; J1.7@118.11,78.74 v1(118.11,499.74)
  Bottom Layer w8: J1.7@118.11,78.74 v1(118.11,499.74)
XSHUNT: J1.3 R13.2 U7.5 | length 6231.7
  Top Layer w6: -670.55,1367 -442,1367 -278,1203 131.3,1203 cw(c131.3,1131.3) 182,1182 cw(c146.15,1146.15) 196.85,1146.15 196.85,885.15 ; 196,886 196.85,885.15 ; v1(196.85,499.74) 196.85,885.15
  Top Layer w8: v1@-875.71,1526 -875.71,1621.87 cw(c-775.71,1621.87) -846.42,1692.58 -677.86,1861.14 ccw(c-748.57,1931.85) -648.57,1931.85 -648.57,1951.59 ccw(c-694.41,1951.59) -662,1984 cw(c-618.9,2027.1) -679.85,2027.1 -679.85,2099.9 -284.96,2781.09 -239,2836 cw(c-193.13,2790.13) -193.13,2855 -142.34,2855 ccw(c-142.34,2902.8) -108.54,2869 -87.29,2890.25 ccw(c-158,2960.96) -58,2960.96 -58,2973.54 ccw(c-119.46,2973.54) -76,3017 cw(c-44.2,3048.8) -89.17,3048.8 -89.17,3112.1 201.5,3613.5 432.4,3844.4 ccw(c361.69,3915.11) 461.69,3915.11 461.69,4029.89 ccw(c361.69,4029.89) 432.4,4100.6 422.23,4110.77 ; v1(-798.55,1450) -744.84,1396.29 ccw(c-674.13,1467) -674.13,1367 -670.55,1367 ; J1.3@196.85,78.74 v1(196.85,499.74) ; U7.5 404.18,4330.99 ccw(c404.18,4320.88) 397.03,4328.03 393,4324 ccw(c397.83,4319.17) 391,4319.17 391,4158.91 ccw(c443.91,4158.91) 406.5,4121.5 ccw(c442.71,4157.71) 422.23,4110.77 ; 422,4111 422.23,4110.77
  Bottom Layer w8: v1(-877,1526) cw(c-877,1520.08) v1@-872.82,1524.27 ; v1@-872.81,1524.27 v1(-798.55,1450) ; J1.3@196.85,78.74 v1(196.85,499.74) ; v1(393,4325) 393,4331.1 cw(c416.9,4331.1) 400,4348 cw(c415.97,4332.03) 415.97,4354.61 454.45,4354.61 cw(c454.45,4335.45) 468,4349 cw(c456.69,4337.69) 472.69,4337.69 R13.2
pads on no net: U3.11 U3.12 U3.13 U3.14 U3.15 U7.8

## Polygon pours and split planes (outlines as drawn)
3V3 on Bottom Layer "3.3V_1" (solid, remove dead copper, pour order 4): -260.83,2868 -250.66,2886.36 -245.88,2891.14 cw(c-210,2855.26) -210,2906 -198.8,2906 cw(c-198.8,2858.21) -165,2892 ccw(c-150.51,2906.49) -150.51,2886 -142.34,2886 ccw(c-142.34,2913.58) -122.84,2894.08 -119.92,2897 -81,2963 -50,3020.41 220,3596 350,3818 ccw(c319.84,3848.17) 362.5,3848.17 362.5,4048 427.5,4048 427.5,3968 428,3846 371,3747 272,3594 177,3391 -66.91,2882.09 cw(c-107.5,2886.58) -112,2846 -137,2846 -172,2855 -204,2868 ccw(c-220.9,2851.11) -220.9,2875 -228,2875 ccw(c-228,2862.18) -237.07,2871.24 -247.32,2861 -249.67,2863.35 ccw(c-260.88,2852.15) -260.88,2868 -250.02,2887
3V3 on Bottom Layer "3.3V_1" (solid, remove dead copper, pour order 2): -299.03,953 ccw(c-299.07,916.4) -325,942.24 -407.37,859.87 cw(c-464.97,917.43) -465,836 -488,836.87 -531.37,840.54 -586.19,849 -625.1,859 -710,892 -772.94,928 -817,962.74 -852,993 -879,1019.83 -920,1068 -953,1122.18 -984,1183.85 -1001.44,1232.83 -1019,1301.68 -1025,1349 -1027,1414 -1023,1467 -1015,1514 -1005,1557 -992,1598 -971,1645 -945,1691 -884,1796 -829.8,1889.64 -826.08,1893.36 cw(c-803.05,1870.32) -803,1902.92 -794.09,1901.67 -781,1899 -770,1894 -734,1875 ccw(c-730.86,1879.5) -729.91,1874.09 -727.7,1874.7 ccw(c-728.35,1877.36) -726,1875.94 -722.61,1880.19 -684.76,1944 ccw(c-691.53,1947.89) -684,1950 -685,1952 ccw(c-688.31,1950.67) -687,1954 -728,1978 -740,1989 cw(c-713.9,2018.2) -753,2016 -752.07,2023.09 -751,2027 -740,2046.09 -726,2069.97 -256.34,2876 -243,2868 -733,2028 -734.87,2019.13 -734.42,2012.84 -730.85,2004.15 -728,1999.01 -719.99,1991.01 -712,1986 -700.15,1978.58 -691,1974 -685,1971 -677.3,1965.3 -669.76,1957 -666.74,1951 -666.74,1944 -673.08,1930.92 -698,1884 -707,1871 -715.94,1862.94 -722.17,1861 -730.16,1859.84 -738,1862 -768.36,1875.94 -784,1881 -792.89,1882 -801.73,1880.19 -809.11,1873.89 -818,1859.59 -886.05,1724.05 -922,1664 -950.5,1611.5 -974,1555 -984,1504 -992,1430 -992,1359 -982,1281 -960.43,1207.43 -929.11,1137.89 -901.5,1083.5 -869,1041.25 -829.8,1005 -764.28,950 -704,912.78 -623,884 -576.26,872.48 -524,865 -475,866 -444.15,876 -422,892.73 -406,913 -389,935 -370,958 -354,975 -336,993 -325,997.62 -285,998 -284,998 -284,953
NetJ1_12 on Bottom Layer "Bottom Layer-NetJ1_12" (solid, remove dead copper, pour order 0): 40,806 40,817.86 ccw(c5.86,817.86) 30,842 24.9,847.1 cw(c48.8,871) 15,871 15,926.5 -39,926.5 -39.3,926.19 -39.3,858.15 ccw(c-24.61,858.15) -35,847.76 -27.78,840.54 ccw(c-19.24,849.07) -19.24,837 -13,837 cw(c-13,810.44) 5.78,829.22 6,829 cw(c-3.66,819.34) 10,819.34 10,806
no net on Mechanical 4 (solid): -284,953

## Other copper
Top Layer:
  rectangle net +5V: -528,878.24 -252,939
  pour cut-out: 0,177.4 0,0 257.9,0 257.9,177.4
Bottom Layer:
  rectangle net 3V3: 419,4274 445,4336.75
  rectangle net +5V: -304,881 -251,938
  rectangle net +5V: -527.69,879 -462,939
  rectangle net 3V3: -325,952.8 92,997.62
  rectangle net +5V: -276,902.17 -55,937.78
  rectangle net NetJ1_11: 47,532 77,894.47
  rectangle net NetJ1_12: 10,532 40,816
  rectangle net 3V3: 378.77,4139.33 432.5,4308.5
  rectangle net 3V3: 362.5,4030 427.5,4308.5
  pour cut-out: -212.98,2669.63 -159.98,2641.63 -160.98,2627.63 -163.98,2619.63 -167.98,2612.63 -173.98,2606.63 -190.98,2572.63 -188.98,2569.63 -71.98,2501.63 -292.98,2111.63 -293.98,2109.63 -330.98,2126.63 -515.98,2234.63 -499.98,2271.39 -294.98,2622.63 -293.98,2625.63 -251.98,2607.63 -236.98,2636.63 -234.21,2649.63 -227.98,2658.63 -221.98,2665.63
  pour cut-out: -634.35,1198.83 cw(c-635.61,1197.57) -633.83,1197.57 -633.83,1025.39 -463.15,1025.39 -463.15,1199.23 -633.69,1199.23
  pour cut-out: 0,177.4 0,0 256.9,0 256.9,177.4

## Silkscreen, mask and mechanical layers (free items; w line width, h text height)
Mechanical 1:
  drawing of 2386 lines, arcs and shapes, not listed
  text "5" at 8156.7,4325.32 h137.8
  text "10,4" at -3062.72,4287.88 h137.8
  text "R2,1" at 506.89,3695.85 h137.8 r16.49
  text "R9,7" at 437.26,2998.71 h137.8 r295.83
  text "44,27" at 1708.78,2900.9 h137.8 r300
  text "44,27" at 6753.43,2783.45 h137.8 r60
  text "10" at 539.61,2504.29 h137.8 r30
  text "10" at -772.78,2485.04 h137.8 r330
  text "79,4" at 5488.08,2228.2 h137.8 r90
  text "65,8" at 5849.36,2115.99 h137.8 r90
  text "R9,7" at -1251.32,1934.38 h137.8 r352.12
  text "0,4" at -2643.99,1476.02 h137.8
  text "10" at 2083.24,1406.29 h137.8 r90
  text "R14,5" at -1410.39,1246.65 h137.8 r19.4
  text "57,74" at 7999.21,512.6 h137.8
Mechanical 2:
  lines w0.5: 648.1,3418.57 648.1,4095.74
Mechanical 3:
  lines w6: 518.57,4228.19 518.57,4247.19
Mechanical 4:
  lines w5: -957.36,1683.09 ccw(c-462.98,1397.65) -463,826.78 -23.39,826.77 cw(c-23.88,802.89) 0,802.41 0,0 255.91,0 255.91,802.77 cw(c279.78,802.89) 279.66,826.77 1239.37,826.77 1239.37,1220.44 -108.39,1220.47 cw(c-108.38,1602.36) -439.1,1793.32 121.28,2763.87 cw(c452,2572.92) 782.73,2763.85 1390.38,1711.31 1646.29,1858.61 1594.5,1948.32 1679.74,1997.53 1128.6,2952.19 1043.36,2902.98 1003.99,2971.17 1089.23,3020.38 860.08,3417.3 452.02,3417.31 cw(c452.02,3499.99) 394.16,3559.04 ccw(c-49.74,4012.89) 464.84,3641.1 ccw(c24.31,3959.43) 503.7,3703.33 ccw(c91.77,3922.61) 519.55,3736.13 ccw(c138.88,3902.12) 532.52,3769.79 ccw(c183.5,3887.15) 542.24,3804.11 ccw(c239.31,3875.17) 550.46,3874 550.46,3952.74 550.46,4393.69 353.61,4393.69 353.61,3952.75 353.61,3913.38 cw(c222.06,3913.41) 350.2,3883.68 cw(c204.05,3917.92) 340.75,3855.9 cw(c158.18,3938.86) 326.37,3829.65 cw(c73.79,3993.55) 308.19,3804.57 cw(c-93.59,4128.16) 287.35,3780.27 cw(c-627.68,4615.35) 264.96,3756.39 242.17,3732.54 ccw(c839.65,3165.01) 220.1,3708.36 ccw(c465.09,3488.64) 182.62,3657.47 -185.21,3020.41 -99.97,2971.2 -139.35,2903.01 -224.58,2952.23 -775.77,1997.6 -690.53,1948.38 -729.91,1880.19 -815.14,1929.41 -957.36,1683.09
Mechanical 12:
  circle w0.5: c-266.51,2360.24 r98.43
  circle w0.5: c1190.18,2360.21 r98.43
  circle w0.5: c-266.51,2360.24 r59.06
  circle w0.5: c1190.18,2360.21 r59.06
  circle w0.5: c953.93,1100.37 r98.43
  circle w0.5: c619.28,1100.38 r98.43
  circle w0.5: c284.64,1100.39 r98.43
  circle w0.5: c-50.01,1100.39 r98.43
  circle w0.5: c953.93,1100.37 r59.06
  circle w0.5: c619.28,1100.38 r59.06
  circle w0.5: c284.64,1100.39 r59.06
  circle w0.5: c-50.01,1100.39 r59.06
  circle w0.5: c953.92,1100.37 r98.43
  circle w0.5: c619.27,1100.38 r98.43
  circle w0.5: c284.63,1100.39 r98.43
  circle w0.5: c-50.02,1100.4 r98.43
  circle w0.5: c953.92,1100.37 r59.06
  circle w0.5: c619.27,1100.38 r59.06
  circle w0.5: c284.63,1100.39 r59.06
  circle w0.5: c-50.02,1100.4 r59.06
  lines w0.5: 3216.56,-822.41 3216.56,-842.1 3413.41,-842.1 3413.41,-822.41 ; 3316.56,4765.63 3316.56,4785.31 3513.41,4785.31 3513.41,4765.63 ; 3452.81,-822.41 3452.81,-842.1 3649.66,-842.1 3649.66,-822.41 ; 3552.81,4765.63 3552.81,4785.31 3749.66,4785.31 3749.66,4765.63 ; 3787.46,-822.41 3787.46,-842.1 3984.31,-842.1 3984.31,-822.41 ; 3887.46,4765.63 3887.46,4785.31 4084.31,4785.31 4084.31,4765.63 ; 3905.61,995.94 3925.29,995.94 ; 3905.61,995.98 3905.61,1192.76 3925.29,1192.79 ; 3905.61,2255.78 3925.29,2255.78 ; 3905.61,2255.81 3905.61,2452.6 ; 3905.61,2452.63 3925.29,2452.63 ; 4122.1,-822.41 4122.1,-842.1 4318.95,-842.1 4318.95,-822.41 ; 4222.1,4765.63 4222.1,4785.31 4418.95,4785.31 4418.95,4765.63 ; 4456.75,-822.41 4456.75,-842.1 4653.6,-842.1 4653.6,-822.41 ; 4556.75,4765.63 4556.75,4785.31 4753.6,4785.31 4753.6,4765.63 ; 4673.25,-822.41 4673.25,-842.1 4870.1,-842.1 4870.1,-822.41 ; 4773.25,4765.63 4773.25,4785.31 4970.1,4785.31 4970.1,4765.63 ; 6284.03,2804.23 cw(c6295.04,2746.21) 6295.04,2805.26 ; 6323.32,2694.36 ccw(c6295.04,2746.21) 6329.47,2698.23 ; 6351.17,2764.56 cw(c6295.04,2746.21) 6353.87,2741.01 ; 6489.53,1528.13 cw(c6531.29,1486.37) 6494.23,1532.35 ; 6489.53,1444.61 ccw(c6531.29,1486.37) 6494.23,1440.39 ; 6568.35,1440.39 ccw(c6531.29,1486.37) 6573.05,1444.61 ; 6568.35,1532.35 cw(c6531.29,1486.37) 6573.05,1528.13 ; 6824.18,1444.62 ccw(c6865.94,1486.38) 6828.88,1440.4 ; 6824.18,1528.14 cw(c6865.94,1486.38) 6828.88,1532.36 ; 6903,1440.4 ccw(c6865.94,1486.38) 6907.7,1444.62 ; 6903,1532.36 cw(c6865.94,1486.38) 6907.7,1528.14 ; 7067.97,2412.23 cw(c7078.98,2354.21) 7078.98,2413.26 ; 7107.26,2302.36 ccw(c7078.98,2354.21) 7113.42,2306.23 ; 7135.11,2372.56 cw(c7078.98,2354.21) 7137.81,2349.01 ; 7158.83,1444.63 ccw(c7200.58,1486.39) 7163.52,1440.41 ; 7158.82,1528.14 cw(c7200.58,1486.39) 7163.52,1532.36 ; 7237.65,1440.41 ccw(c7200.58,1486.39) 7242.34,1444.63 ; 7237.64,1532.37 cw(c7200.58,1486.39) 7242.34,1528.15 ; 7273.48,1052.61 ccw(c7315.24,1094.37) 7278.18,1048.39 ; 7273.48,1136.13 cw(c7315.24,1094.37) 7278.17,1140.35 ; 7352.3,1048.39 ccw(c7315.24,1094.37) 7357,1052.61 ; 7352.3,1140.35 cw(c7315.24,1094.37) 7356.99,1136.13 ; 7493.47,1444.64 ccw(c7535.23,1486.4) 7498.17,1440.42 ; 7493.47,1528.15 cw(c7535.23,1486.4) 7498.17,1532.37 ; 7572.29,1440.42 ccw(c7535.23,1486.4) 7576.99,1444.64 ; 7572.29,1532.37 cw(c7535.23,1486.4) 7576.99,1528.15 ; 7608.12,1052.62 ccw(c7649.88,1094.38) 7612.82,1048.4 ; 7608.12,1136.13 cw(c7649.88,1094.38) 7612.82,1140.35 ; 7686.94,1048.4 ccw(c7649.88,1094.38) 7691.64,1052.62 ; 7686.94,1140.36 cw(c7649.88,1094.38) 7691.64,1136.14 ; 7803.52,2774.63 cw(c7751.73,2746.24) 7806.77,2767.65 ; 7942.77,1052.63 ccw(c7984.53,1094.39) 7947.47,1048.41 ; 7942.77,1136.14 cw(c7984.53,1094.39) 7947.47,1140.36 ; 8021.59,1048.41 ccw(c7984.53,1094.39) 8026.29,1052.63 ; 8021.59,1140.37 cw(c7984.53,1094.39) 8026.28,1136.15 ; 8277.42,1052.63 ccw(c8319.17,1094.39) 8282.11,1048.41 ; 8277.41,1136.15 cw(c8319.17,1094.39) 8282.11,1140.37 ; 8356.23,1140.37 cw(c8319.17,1094.39) 8360.93,1136.15 ; 8356.23,1048.42 ccw(c8319.17,1094.39) 8360.93,1052.64 ; 8587.46,2382.63 cw(c8535.68,2354.24) 8590.71,2375.65
Drill Drawing:
  text "PWB, LED SENSE FLEX" at 7553.47,-3644.84 h157.48
  text "PWB-020218-001" at 7740.48,-3970.63 h127.95
  text "1" at 10165.68,-4029.68 h78.74
  text "1" at 9976.7,-4033.62 h78.74
Mechanical 17:
  text "PWA, LED SENSE FLEX" at 7596.1,-3719.43 h157.48
  text "PWA-020218-001" at 7790.1,-4010.43 h127.95
  text "1" at 9968.83,-4021.81 h59.06
  text "1" at 10157.8,-4021.81 h59.06
  text "NOTES: /  / 1. ALL ASSEMBLY MATERIALS TO BE RoHS COMPLIANT. /  / 2. MATERIAL: /           • FLEXIBLE METAL CLAD DIELECTRIC IAW                 /             IPC-4204/11 E1E2 O0/0 CU W7 T/T /           • STIFFENER IAW IPC-4203/1-E1E8M1 /  / 3. FINISH:  IMMERSION GOLD /  / ALL EXPOSED CONDUCTIVE PATTERN AREAS NOT COVERED WITH COVERLAY MATERIAL OR OTHER PLATING  / SHALL BE IMMERSION GOLD (0.000030-0.000090 mm) OVER ELECTROLESS NICKEL (0.001-0.006 mm). /  / 4. LEGEND SHALL BE WHITE, PERMANENT, ORGANIC, NON-CONDUCTIVE UV OR EPOXY TYPE INK APPLIED  / TO THE TOP SIDE OF THE BOARD. THERE SHALL BE NO LEGEND ON ANY SOLDERABLE COMPONENT LAND. /  / 5. ALL ASSEMBLY MATERIALS TO BE RoHS COMPLIANT. /  / 6. ANY LABELS OR COMPOSITION OF, APPLIED TO THE BOARD NEED TO BE APPROVIED BY AIRZAI /  / 7. MINIMUM TRACE WIDTHS: /           EXTERNAL: 0.203 mm  INTERNAL: N/A /  / 8. MINIMUM SPACE BETWEEN FEATURES: /          EXTERNAL: 0.15 mm  INTERNAL: N/A /  / 9. Overall Board Thickness: 0.1mm" at -4011,-6962.97 h78.74
Mechanical 18:
  lines w5: -4122.85,-1925.75 -3922.85,-1925.75 ; -4122.85,449.25 -3922.85,449.25 ; -4122.85,2824.25 -3922.85,2824.25 ; -1622.85,-4300.75 -1622.85,-4100.75 ; -1622.85,4999.25 -1622.85,5199.25 ; 877.15,-4300.75 877.15,-4100.75 ; 877.15,4999.25 877.15,5199.25 ; 3377.15,-4300.75 3377.15,-4100.75 ; 3377.15,4999.25 3377.15,5199.25 ; 5877.15,-4300.75 5877.15,-4100.75 ; 5877.15,4999.25 5877.15,5199.25 ; 6176.35,-3802.97 10676.35,-3802.97 ; 6176.35,-3561.23 7247.02,-3561.23 ; 6176.35,-3327.18 7247.02,-3327.18 ; 6176.35,-3116.35 7247.02,-3116.35 ; 6177.15,-4100.75 10677.15,-4100.75 ; 6802.14,-4103.95 6802.14,-2903.95 ; 7247.02,-4102.97 7247.02,-2902.97 ; 7247.02,-3436.04 10676.2,-3436.04 ; 7586.98,-2902.97 10676.35,-2902.97 ; 7676.35,-2902.97 6176.35,-2902.97 ; 8377.15,-4300.75 8377.15,-4100.75 ; 8377.15,4999.25 8377.15,5199.25 ; 10299.97,-4102.97 10299.97,-3802.97 ; 10677.15,-2900.75 10677.15,-4100.75 ; 10677.15,-1925.75 10877.15,-1925.75 ; 10677.15,449.25 10877.15,449.25 ; 10677.15,2824.25 10877.15,2824.25 ; 4776.35,-4102.97 6176.35,-4102.97 ; 4776.35,-4102.97 6176.35,-4102.97 ; 4776.35,-4102.97 4776.35,-2902.97 6176.35,-2902.97 ; 6176.35,-4102.97 10676.35,-4102.97 ; 6176.35,-4102.97 10676.35,-4102.97 ; 6176.35,-4102.97 6176.35,-2902.97 ; 10676.35,-4102.97 10676.35,-2902.97 ; 10676.35,-4102.97 10676.35,-2902.97 ; 10677.15,-4100.75 10677.15,4999.25 -3922.85,4999.25 -3922.85,-4100.75 10677.15,-4100.75 ; -4122.85,-4300.75 -4122.85,5199.25 10877.15,5199.25 10877.15,-4300.75 -4122.85,-4300.75
  text "1" at -2891.51,5069.25 h70
  text "2" at -395.85,5069.25 h70
  text "3" at 2093.49,5069.25 h70
  text "4" at 4600.16,5069.25 h70
  text "5" at 7099.15,5069.25 h70
  text "6" at 9604.15,5069.25 h70
  text "A" at -4047.85,3926.25 h70
  text "A" at 10752.15,3926.25 h70
  text "B" at -4047.85,1546.25 h70
  text "B" at 10752.15,1546.25 h70
  text "C" at -4047.85,-828.75 h70
  text "C" at 10752.15,-828.75 h70
  text "AIRZAI PROPRIETARY & CONFIDENTIAL" at 6332.27,-2792.09 h127.95
  text "DATE:" at 6832.65,-2965.17 h45
  text "ENGINEER:" at 6198.79,-2971.47 h45
  text "UNLESS OTHERWISE SPECIFIED" at 4875.96,-3032.1 h59.06
  text "05/13/19" at 6839.98,-3073.78 h59.06
  text "FD" at 6391.67,-3080.05 h78.74
  text "DIMENSIONS ARE IN MM" at 4998.01,-3158.08 h59.06
  text "PCB DESIGNER:" at 6194.86,-3179.86 h45
  text "DATE:" at 6820.84,-3181.71 h45
  text "D" at -4047.85,-3198.75 h70
  text "D" at 10752.15,-3198.75 h70
  text "AIRZAI" at 7537.98,-3236.97 h127.95
  text "TOLERANCES" at 5198.79,-3284.07 h59.06
  text "05/13/19" at 6839.98,-3288.35 h59.06
  text "DFM" at 6365.29,-3289.93 h78.74
  text "DATE:" at 6820.84,-3394.3 h45
  text "CHECK" at 6194.86,-3396.39 h45
  text "ANGULAR" at 5683.05,-3441.55 h59.06
  text "DECIMALS" at 4879.9,-3453.36 h59.06
  text "TITLE:" at 7298.8,-3499.77 h45
  text "FD" at 6431.04,-3513.12 h78.74
  text ".XX +/- .127MM" at 4832.65,-3610.84 h59.06
  text "+/-" at 5671.23,-3614.78 h59.06
  text "REL" at 6206.67,-3627.38 h45
  text "DATE:" at 6836.59,-3634.46 h45
  text "FD" at 6421.2,-3729.66 h78.74
  text ".XXX +/- .080MM" at 4820.84,-3772.26 h59.06
  text "REV:" at 10322.42,-3866.75 h45
  text "SCALE:" at 6842.1,-3867.53 h45
  text "DWG NO:" at 7293.28,-3875.41 h45
  text "SIZE" at 6206.67,-3878.56 h45
  text "B" at 6410.41,-4009.15 h120
  text "DO NOT SCALE DRAWING" at 4875.96,-4012.41 h70.87
  text "A" at 10406.09,-4028.31 h120
  text "1:1" at 6890.72,-4032.77 h120
  text "SHEET" at 9757.85,-4064.38 h45
  text "OF" at 10021.63,-4064.38 h45
  text "1" at -2891.51,-4230.75 h70
  text "2" at -395.85,-4230.75 h70
  text "3" at 2093.49,-4230.75 h70
  text "4" at 4600.16,-4230.75 h70
  text "5" at 7099.15,-4230.75 h70
  text "6" at 9604.15,-4230.75 h70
